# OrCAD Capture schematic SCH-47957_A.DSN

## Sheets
1 01_TITLE: title: OM29110ARD-B; rev: A; note: SCH-47957 PDF: SPF-47957
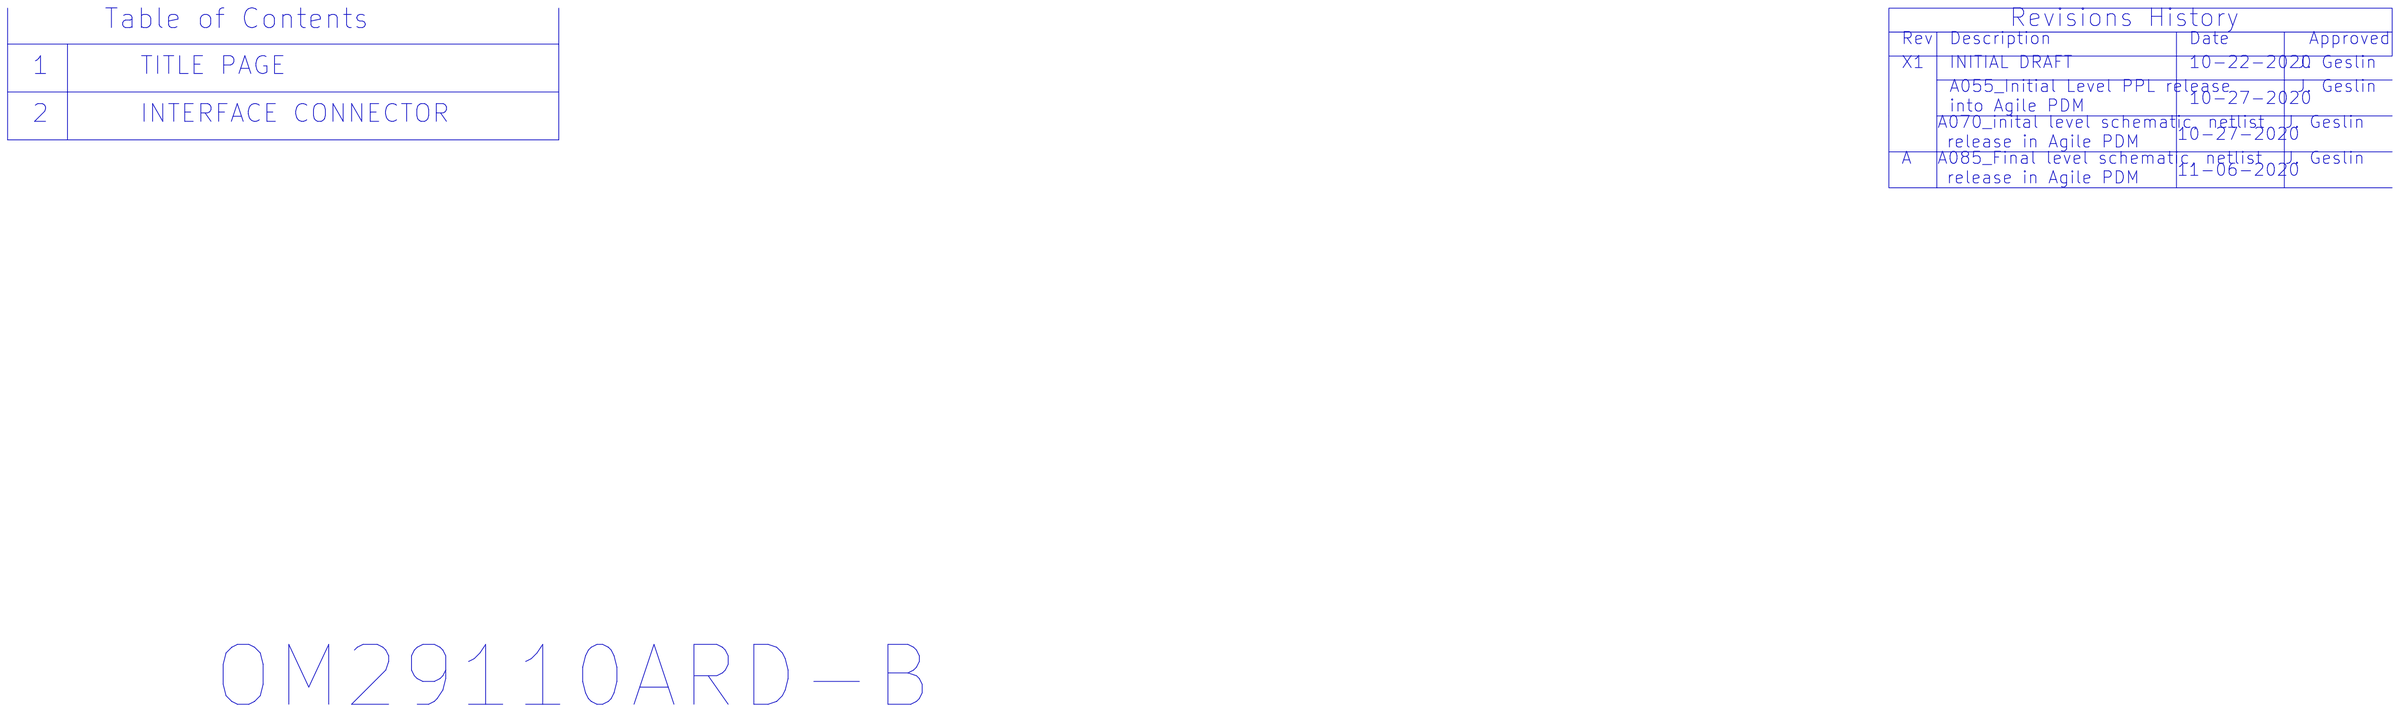
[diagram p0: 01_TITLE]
2 02_INTERFACE CONNECTORS: size C; company: NXP Semiconductors; note: 6501 William Cannon Drive West; note: Austin, TX 78735-8598
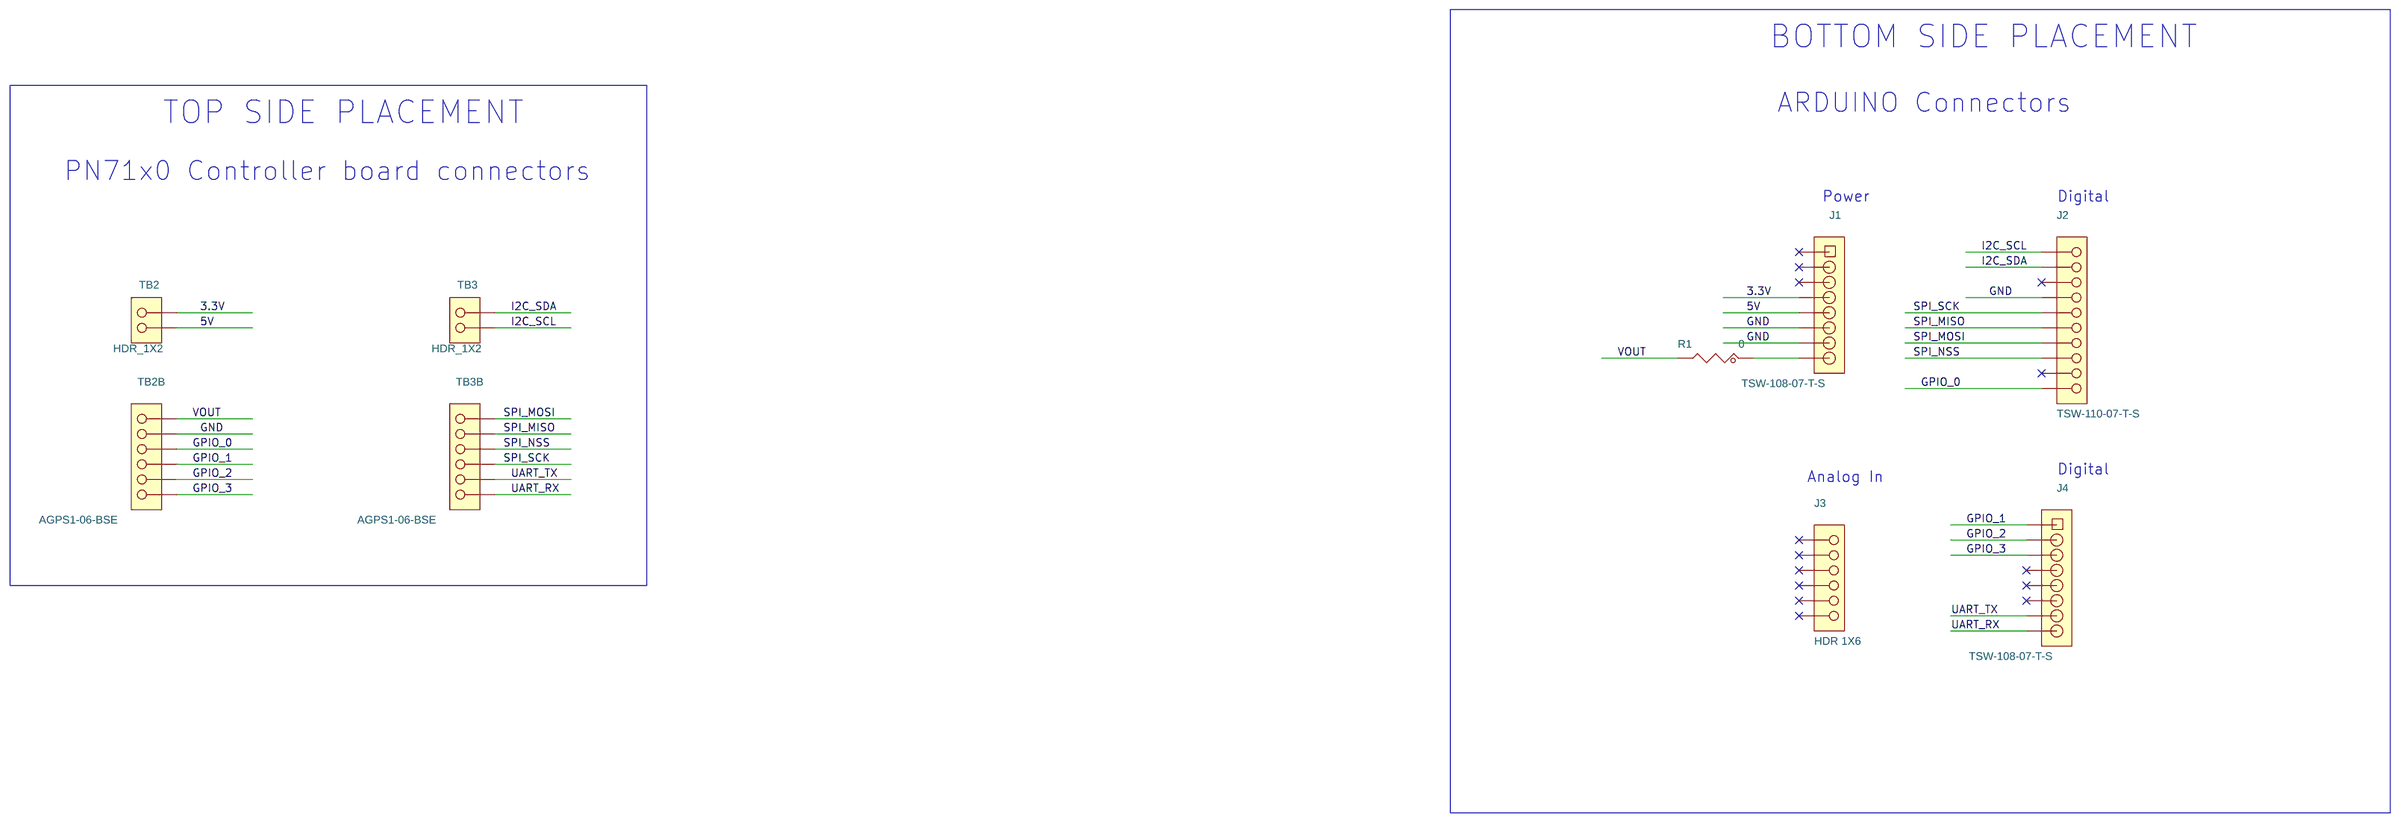
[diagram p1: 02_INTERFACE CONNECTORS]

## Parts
J1  TSW-108-07-T-S  [JUMP1X8-6040]
J2  TSW-110-07-T-S  [hdr110]
J3  HDR 1X6  [hdr106_th_tsw]
J4  TSW-108-07-T-S  [JUMP1X8-6040]
R1  0  [RC0402_25]
TB2  HDR_1X2  [skt1x2_2p54_th_bse]
TB2B  AGPS1-06-BSE  [skt1x6_2p54_th_bse]
TB3  HDR_1X2  [skt1x2_2p54_th_bse]
TB3B  AGPS1-06-BSE  [skt1x6_2p54_th_bse]

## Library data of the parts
J1 J4 = HDR-1X8: HDR 1X8 TH 100MIL SP 343H SN 100L; AGILE_PN: 210-80882; CAD_APPROVED: Yes; HEIGHT: 8.71MM; MFG_NAME01: SAMTEC; Package Size: 20.32 x 2.54 mm; ROHS: Yes
J2 = CONN_HDR_10X1: HDR 1X10 TH 100MIL SP 343H SN 100L; AGILE_PN: 210-80883; CAD_APPROVED: Yes; HEIGHT: 8.71MM; MFG_NAME01: SAMTEC; ROHS: Yes
J3 = CONN_HDR_6X1: HDR 1X6 TH 100MIL SP 330H SN 100L; AGILE_PN: 210-80604; CAD_APPROVED: Yes; HEIGHT: 8.38MM; MFG_NAME01: SAMTEC; MFG_PN01: TSW-106-07-T-S; ROHS: Yes
R1 = RES: RES MF ZERO OHM 1/10W -- 0402; AGILE_PN: 470-79965; CAD_APPROVED: Yes; FPLIST: RC0402_25,RC0402_HD,RC0402_X2,0402_CC; HEIGHT: 0.4MM; MFG_NAME01: PANASONIC; MFG_PN01: ERJ-2GE0R00X; ROHS: Yes; Temp Range: –55 °C to +155 °C; VOLTAGE: 1/10W
TB2 TB3 = CONN_HDR_2X1: CON 1X2 SKT TH 100MIL SP 276H SN 196L; AGILE_PN: 210-82543; CAD_APPROVED: Yes; Contact Voltage: 1000Vrms; HEIGHT: 7.0MM; MFG_NAME01: ANTELEC; MFG_PN01: AGPS1-02-BSE-1MM3; Package Size: 5.08 x2.5mm; Package Type: CON HDR TH; ROHS: Yes; Temp Range: -55C to +125C
TB2B TB3B = CONN_HDR_6X1: CON 1X6 TB TH 100MIL 276H SN 196L; AGILE_PN: 210-81709; CAD_APPROVED: Yes; HEIGHT: 7MM; MFG_NAME01: ANTELEC; ROHS: Yes; Temp Range: -55°C ~ 125°C

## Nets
3.3V: J1.4 TB2.1
5V: J1.5 TB2.2
GND: J1.6 J1.7 J2.4 TB2B.2
GPIO_0: J2.10 TB2B.3
GPIO_1: J4.1 TB2B.4
GPIO_2: J4.2 TB2B.5
GPIO_3: J4.3 TB2B.6
I2C_SCL: J2.1 TB3.2
I2C_SDA: J2.2 TB3.1
SPI_MISO: J2.6 TB3B.2
SPI_MOSI: J2.7 TB3B.1
SPI_NSS: J2.8 TB3B.3
SPI_SCK: J2.5 TB3B.4
UART_RX: J4.8 TB3B.6
UART_TX: J4.7 TB3B.5
VOUT: R1.2 TB2B.1
N16624029: J1.8 R1.1

Not connected (* = marked no-connect by the designer): J1 1* 2* 3*; J2 3* 9*; J3 1* 2* 3* 4* 5* 6*; J4 4* 5* 6*

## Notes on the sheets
sheet 1
- Table of Contents
- Revisions History
- Rev
- Description
- Date
- Approved
- 1
- TITLE PAGE
- X1
- INITIAL DRAFT
- 10-22-2020
- J. Geslin
- A055_Initial Level PPL release
  into Agile PDM
- J. Geslin
- 10-27-2020
- 2
- INTERFACE CONNECTOR
- A070_inital level schematic, netlist
   release in Agile PDM
- J. Geslin
- 10-27-2020
- A
- A085_Final level schematic, netlist
   release in Agile PDM
- J. Geslin
- 11-06-2020
- OM29110ARD-B
sheet 2
- BOTTOM SIDE PLACEMENT
- TOP SIDE PLACEMENT
- ARDUINO Connectors
- PN71x0 Controller board connectors
- Power
- Digital
- Analog In
- Digital
